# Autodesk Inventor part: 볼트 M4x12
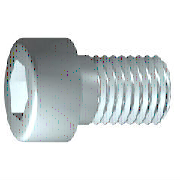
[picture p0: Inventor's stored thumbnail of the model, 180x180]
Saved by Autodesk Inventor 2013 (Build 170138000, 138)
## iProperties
IsCustomPart: 0
Created: 2015-12
Part Number: 볼트 M4x12
Material: 강철, 연강
Description: 6각머리 태핑 나사
Document SubType Name: Modeling
Standard: KS B 1003
Designer: mdu
Standards Organization: KS
Language: ko-KR
Size Designation: M 4 x 12
Categories: <MemberInstance><Categories><Category DisplayName="조임쇠" InternalName="e4da775c-781d-43d5-af7c-5136215cf5a6" Mnemonic="FSTN"><Category DisplayName="볼트" InternalN
Density: 7.86 g/cm^3
Mass: 2.23465 g
Surface Area: 3.30853 cm^2
Volume: 0.284306 cm^3
Author: mdu
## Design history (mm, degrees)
sketch "스케치1"
  geometry: L1 (-1, 0)-(12, 0); L2 (12, 0)-(12, 2); L3 (12, 2)-(1.75, 2); L4 (1.75, 2)-(1.32, 2); L5 (1.32, 2)-(0, 2); L6 (0, 2)-(0, 3.5); L7 (0, 3.5)-(-4, 3.5); L8 (-4, 3.5)-(-4, 1.732); L9 (-4, 1.732)-(-2, 1.732); L10 (-2, 1.732)-(-1, 0); L11 (-7.2, 0)-(15.2, 0) reference; L12 (0, -0.7)-(0, 4.2) reference; L13 (1.75, 2)-(0, 2)
  constraints: 22 end point, 6 parallel, 2 collinear, 2 perpendicular, 1 horizontal, 1 point on line
  dimensions: "d1" = 10.25 distance from line of L3.end L2 (= GEL); "d2" = 0.42952 distance of L4.end L3.end (computed from GAL); "d3" = 4 distance between parallel lines of L8 L6 (= KOH); "d4" = 2 distance of L8.end L9.end (= INTI); "d5" = 60 deg angle of L10 L1; "d6" = 4 diameter of L3 L1 (= GD); "d7" = 4 diameter of L5 L1 (= BDM); "d8" = 3.4641 diameter of L9 L1 (= 1.1547 x SW); "d9" = 7 diameter of L7 L1 (= KOD); "d26" = 12 distance between parallel lines of L12 L2 (= NLG)
revolve "본체" sketch "스케치1" stored, may be unused: angle "d10" = 90 deg
sketch "스케치2"
  geometry: L1 (0, -4.9)-(0, 4.9) reference; L2 (-4.9, 0)-(4.9, 0) reference; L3 (1.732, 0)-(0.866, -1.5); L4 (0.866, -1.5)-(-0.866, -1.5); L5 (-0.866, -1.5)-(-1.732, 0); L6 (-1.732, 0)-(-0.866, 1.5); L7 (-0.866, 1.5)-(0.866, 1.5); L8 (0.866, 1.5)-(1.732, 0); 2 further points
  constraints: 12 end point, 1 coincident, 1 horizontal alignment, 1 point on line, 12 other
extrude "슬롯" join sketch "스케치2" stored distance "d11" = 10; taper "d12" = 0 deg
workplane "Work Plane1"
fillet "Fillet2" dims "d30" = 0.1 (= R)
body "Solid1"
fillet "모깎기1" dims "d17" = 0.4 (= RR)
feature "스레드" dims "d13" = 10.25 (= GEL), "d14" = 0
chamfer "모따기1" distance "d15" = 0.42941 (= -0.5 x SPD + 0.5 x GD); stored, may be unused: second distance "d16" = 0.42941 (= GUL), angle "d27" = 45 deg
other parameters: "GD" = 4 (= NND) [user parameter; used in 2 equation terms], "NLG" = 12 [user parameter; used in 1 equation term], "GEL" = 10.25 [user parameter; used in 2 equation terms], "KOD" = 7 [user parameter; used in 1 equation term], "KOH" = 4 [user parameter; used in 1 equation term], "INTI" = 2 [user parameter; used in 1 equation term], "GAL" = 0.42941 (= 0.61345 x PTC) [user parameter; used in 1 equation term], "GUL" = 0.42941 (= 0.61345 x PTC) [user parameter; used in 1 equation term], "BDM" = 4 (= NND) [user parameter; used in 1 equation term], "SW" = 3 [user parameter; used in 2 equation terms], "RR" = 0.4 [user parameter; used in 1 equation term], "SPD" = 3.14117 (= NND - 1.2269 x PTC) [user parameter; used in 1 equation term], "d19" = 0, "d28" = 0, "d29" = 0, "R" = 0.1 [user parameter; used in 1 equation term], "PHH" = 0.2 [user parameter], "GD1" = 3.14117 (= THREADDIA - 1.2269 x PTC) [user parameter], "THREADDIA" = 4 [user parameter; used in 1 equation term], "FAWI" = 45 deg [user parameter], "TPU" = 14.28571 (computed from PTC) [user parameter], "PTC" = 0.7 [user parameter; used in 5 equation terms], "NND" = 4 [user parameter; used in 3 equation terms], "TOA" = 30 deg [user parameter], "E0" = 3.465 (= 1.155 x SW) [user parameter]
